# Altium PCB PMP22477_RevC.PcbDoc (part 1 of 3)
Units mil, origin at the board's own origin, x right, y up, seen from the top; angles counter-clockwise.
Board outline 5000 x 3000 mil, 4 copper layers (Top Layer, Signal Layer 1, Signal Layer 2, Bottom Layer), stack 61.2 mil thick; 191 components, 134 nets, 569 pads, 237 vias.
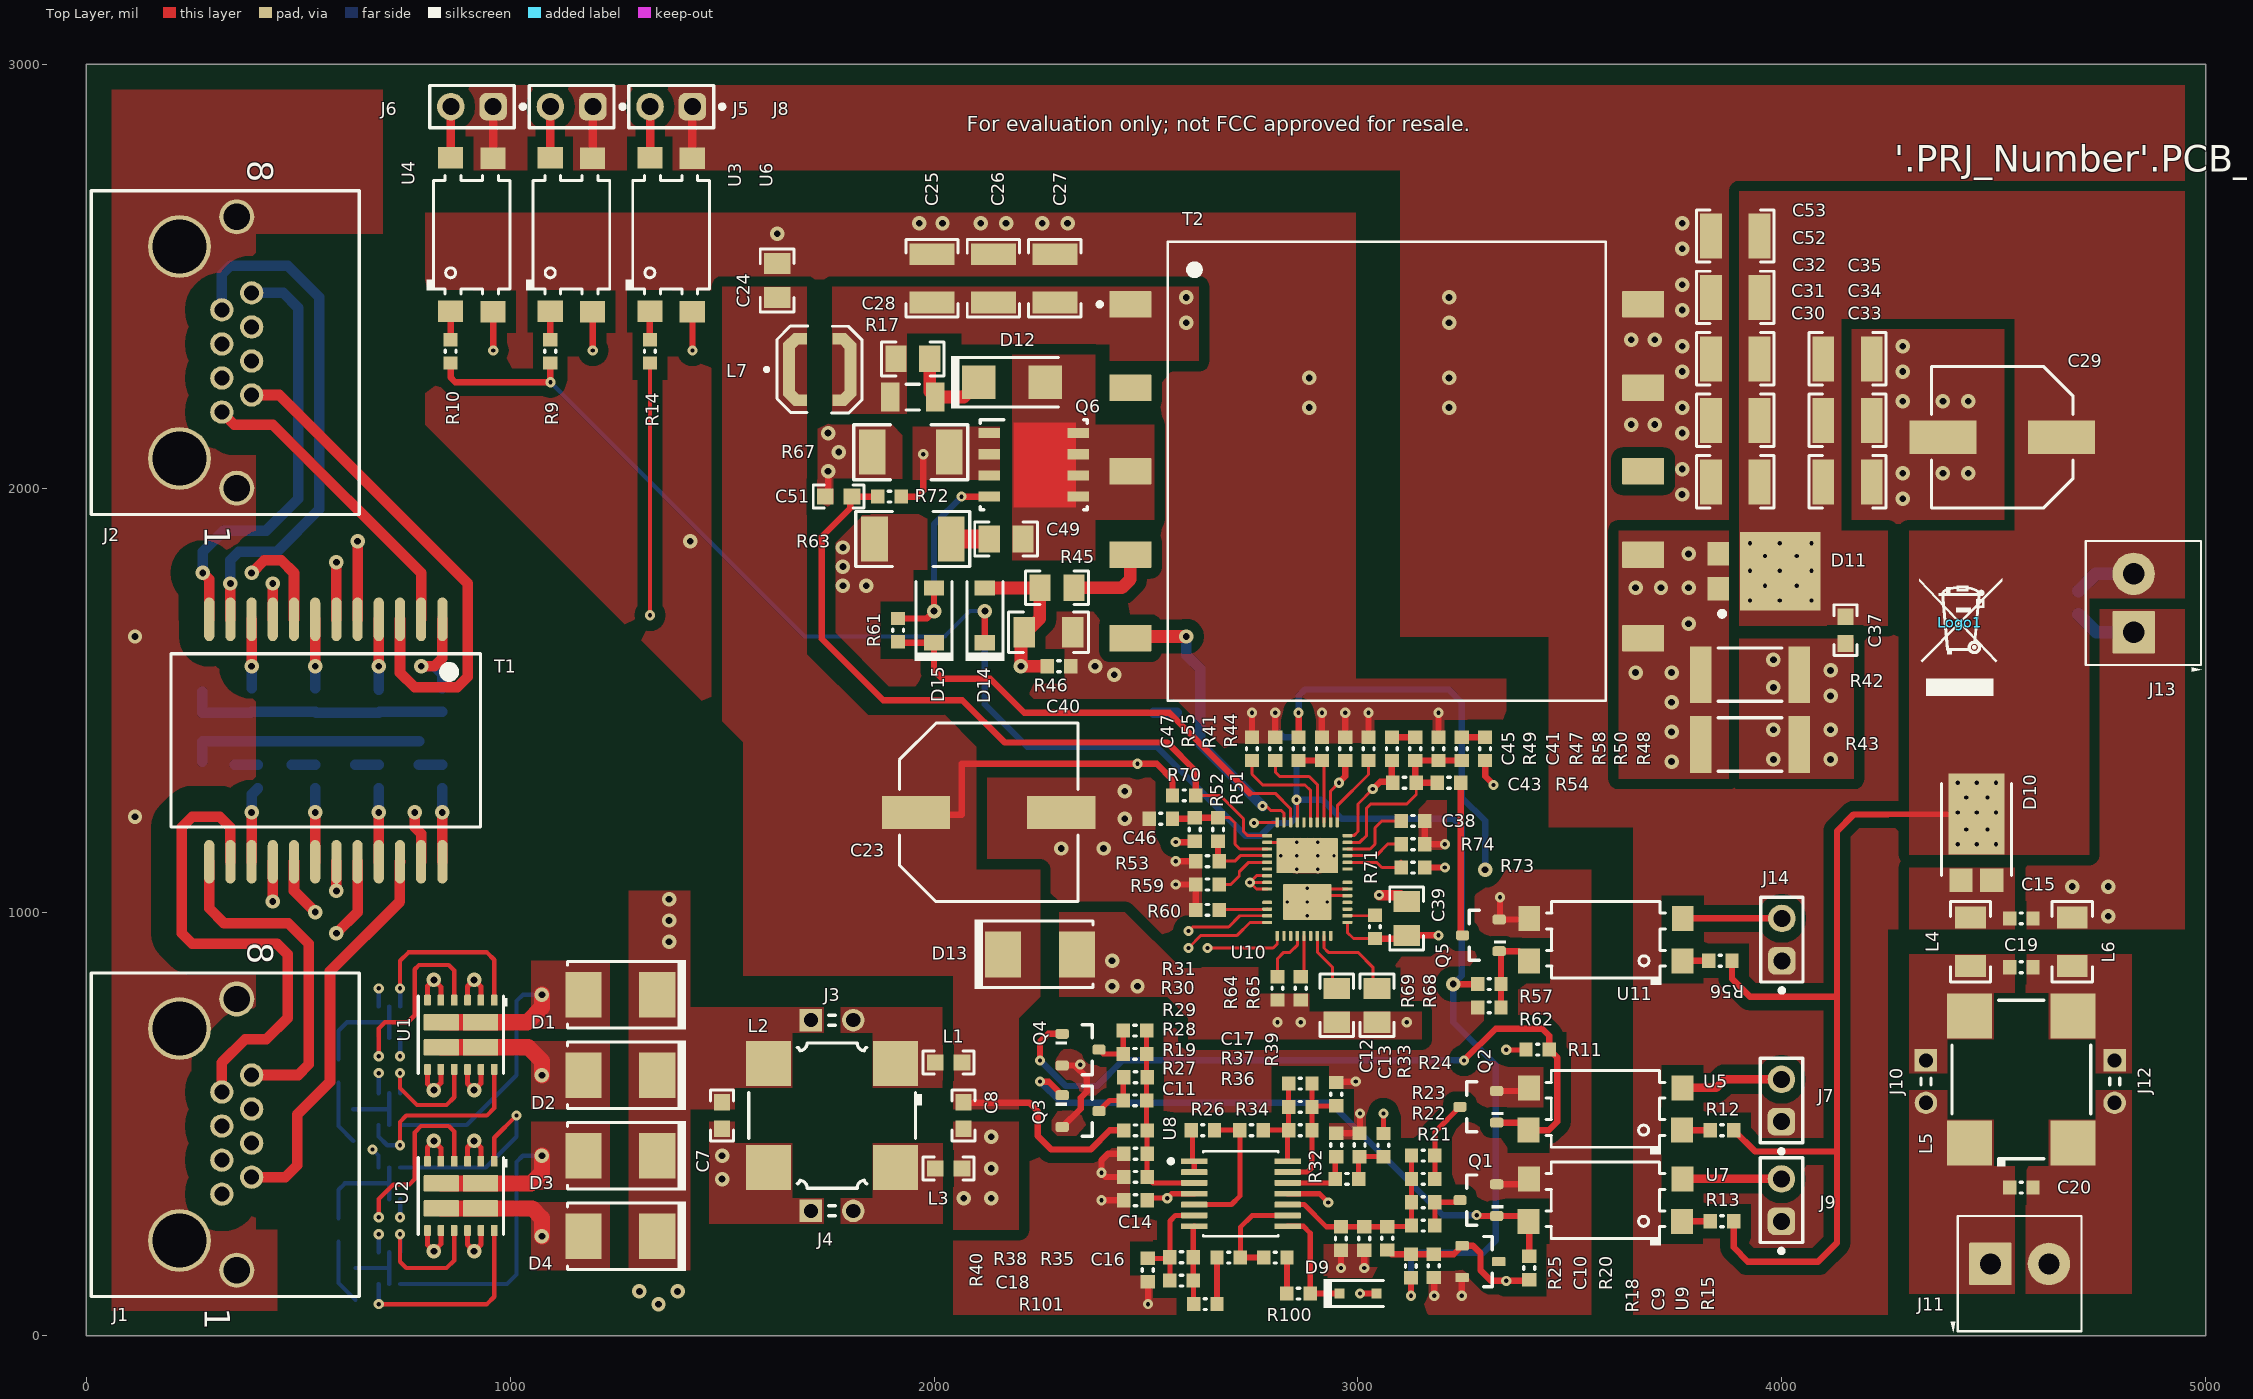
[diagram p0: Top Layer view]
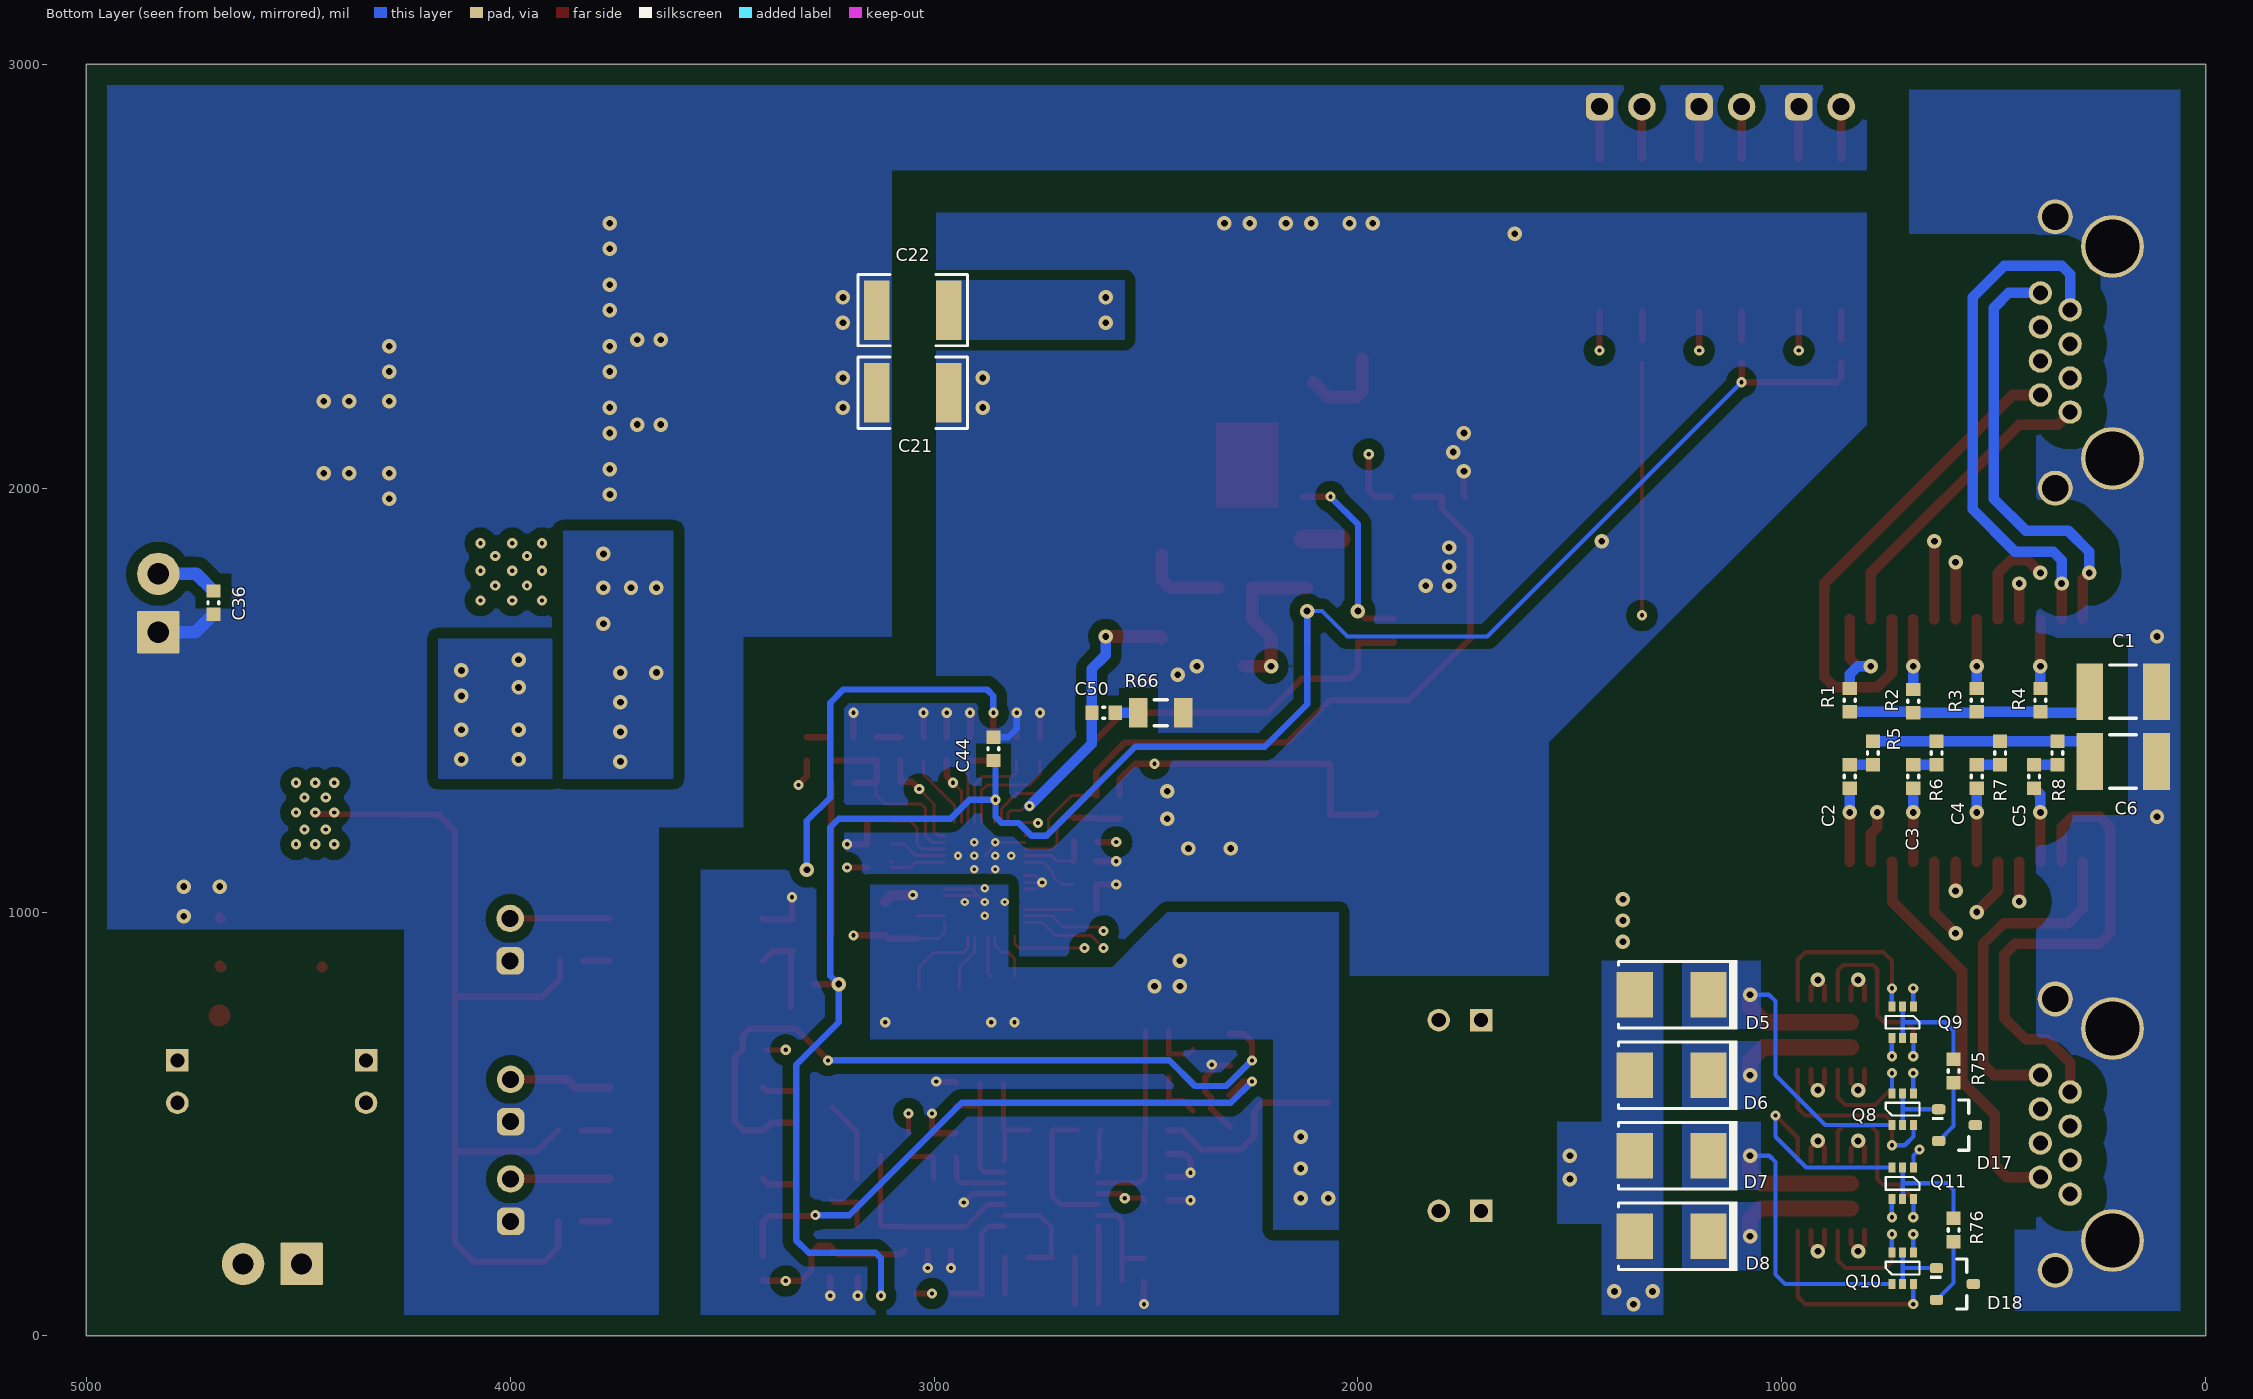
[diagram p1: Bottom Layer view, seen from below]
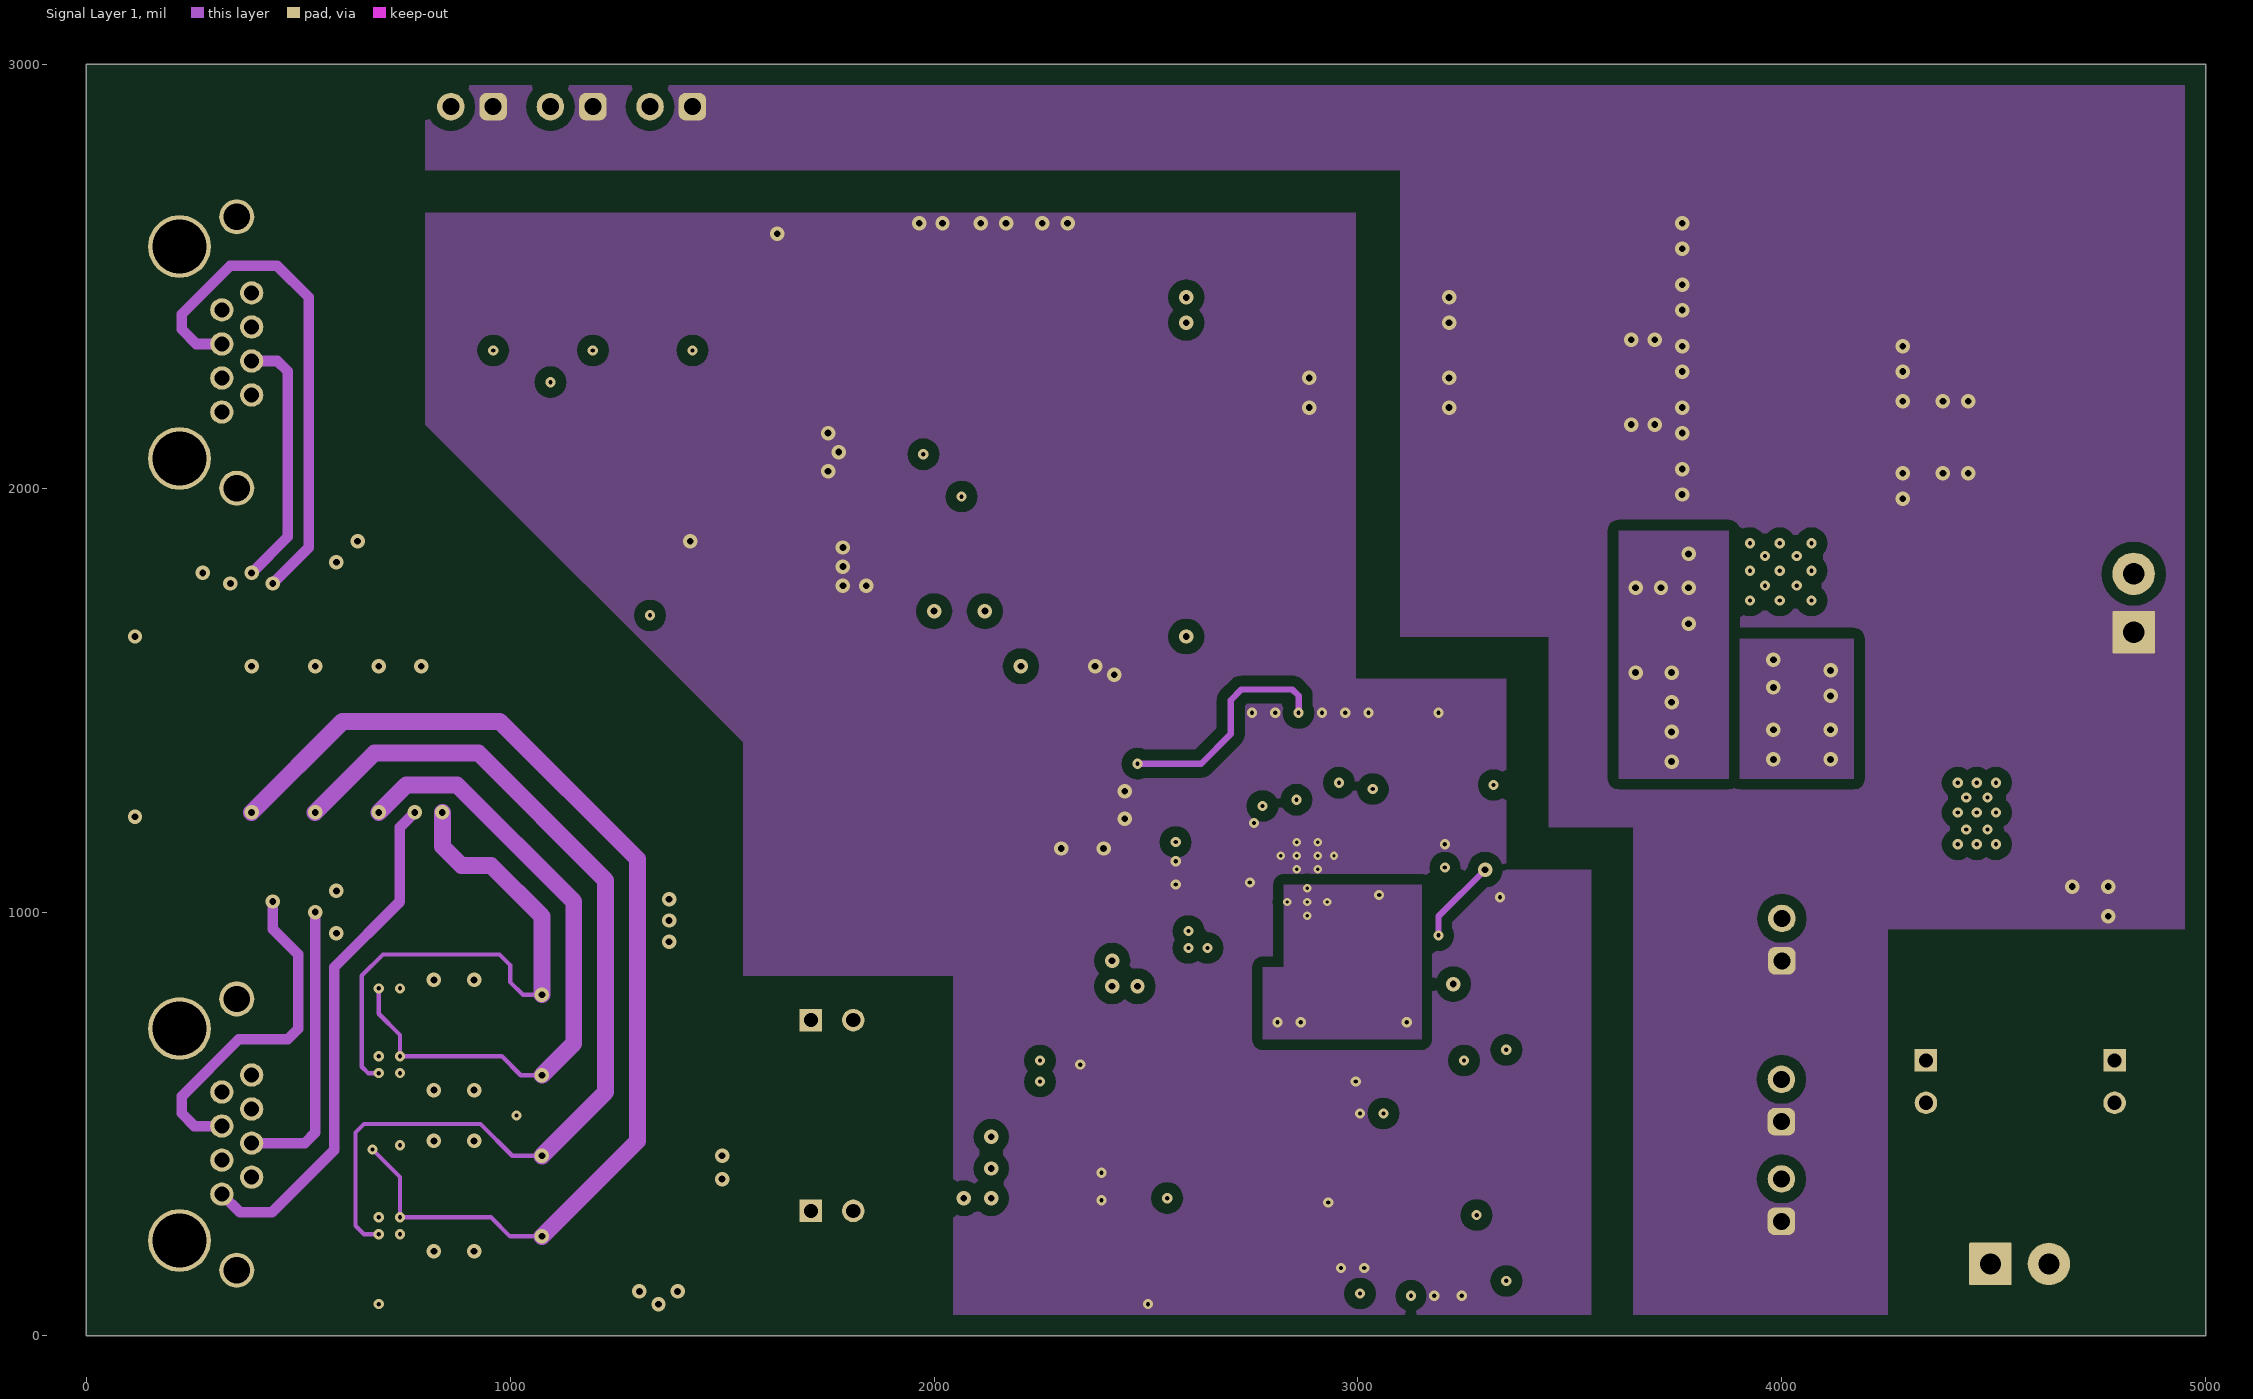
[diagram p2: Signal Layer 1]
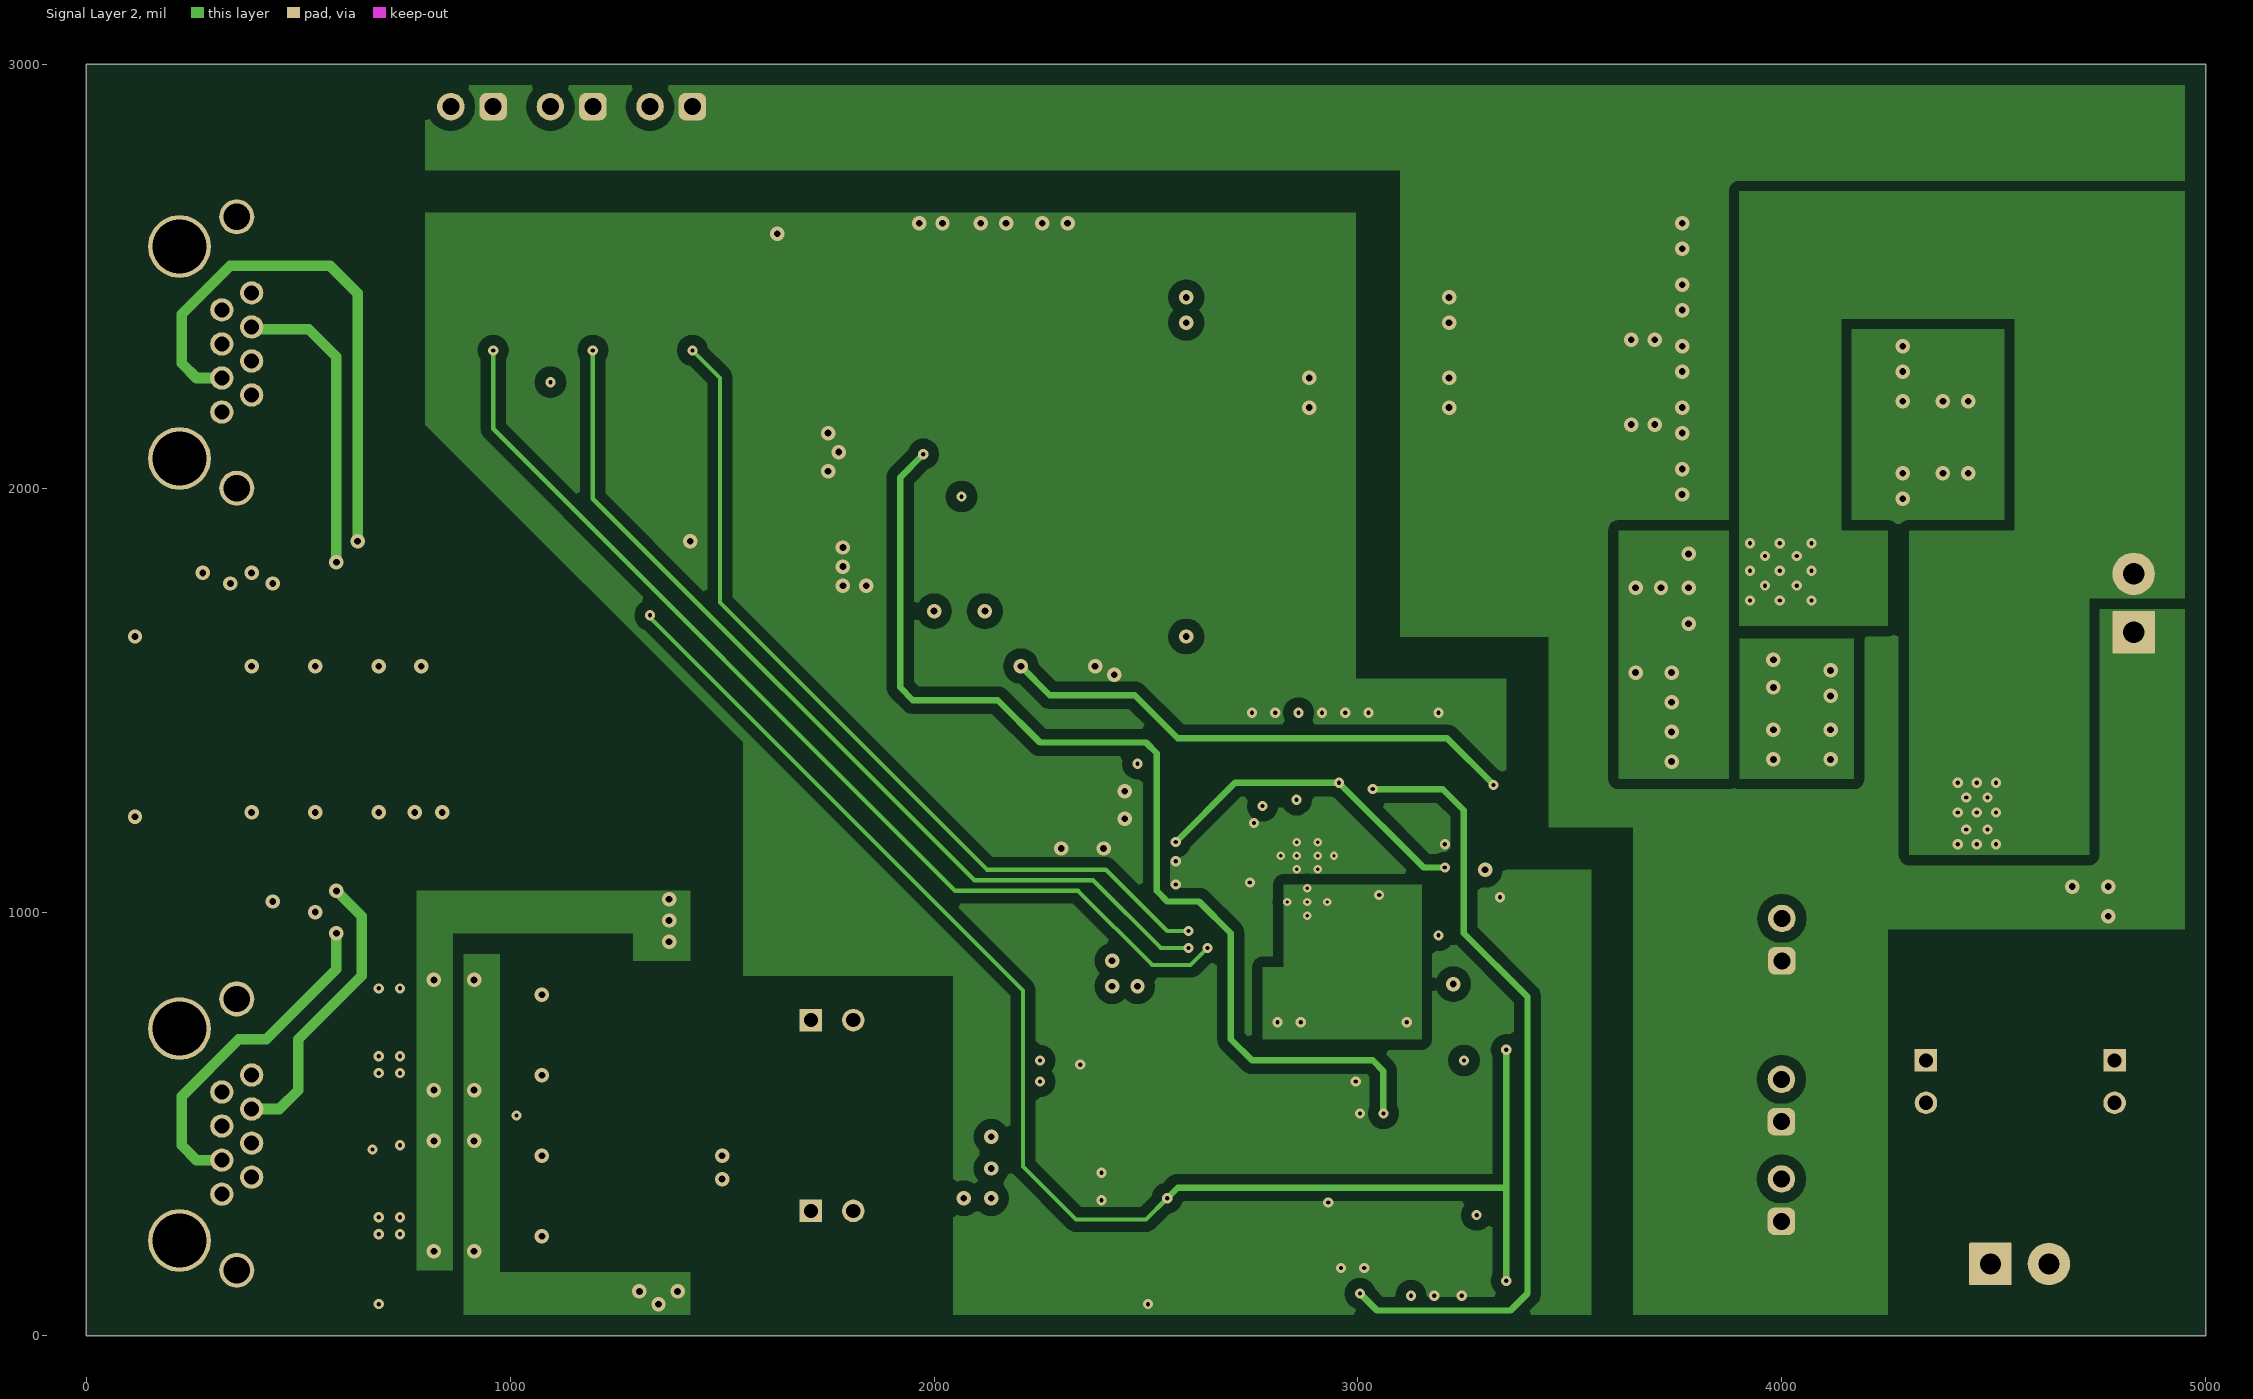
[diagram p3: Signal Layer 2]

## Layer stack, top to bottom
Top Solder: solder mask 0.4, Solder Resist, Dk 3.5
Top Layer: signal copper 2.8
Dielectric1: core 15, FR-4, Dk 4.8
Signal Layer 1: signal copper 2.8
Dielectric 2: prepreg 20, Dk 4.2
Signal Layer 2: signal copper 2.8
Dielectric 3: core 15, Dk 4.2
Bottom Layer: signal copper 2.8
Bottom Solder: solder mask 0.4, Solder Resist, Dk 3.5

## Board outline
0,0 5000,0 5000,3000 0,3000

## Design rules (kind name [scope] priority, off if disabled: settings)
AcuteAngle [All] p1: minimum=4.50000000000000E+0001 checktracksonly=FALSE
AssemblyTestPointUsage [All] p1: valid=2
BoardOutlineClearance BoardOutlineClearance_MountingHoles [OnCopper and InComponentClass('Mounting Holes')] p1: gap=39.37 ignorepadtopadclearanceinfootprint=FALSE
BoardOutlineClearance BoardOutlineClearance_Poly [OnCopper and IsPoly] p2: gap=25 ignorepadtopadclearanceinfootprint=FALSE
BoardOutlineClearance [OnCopper and Not InComponentClass('Logo') and not InComponentClass('FiducialMark') and not InRegion(1000,500,4000,800) and not InPoly] p3: gap=50 ignorepadtopadclearanceinfootprint=FALSE
Clearance Clearance_2 [InNamedPolygon('BOTTOM_LAYER_BSP_P106')] p1: gap=60 ignorepadtopadclearanceinfootprint=FALSE
Clearance Clearance_1 [InNamedPolygon('TOP_LAYER_BSP_P104')] p2: gap=60 ignorepadtopadclearanceinfootprint=FALSE
Clearance Clearance_Keepouts [((IsTrack Or IsArc) And Not InPoly) And IsFree and IsKeepOut vs ((IsTrack Or IsArc) And Not InPoly) And IsFree and IsKeepOut] p3: gap=0 ignorepadtopadclearanceinfootprint=FALSE
Clearance Clearance_Poly [InPolygon] p4: gap=25 ignorepadtopadclearanceinfootprint=TRUE
Clearance Clearance_FiducialMark [IsKeepOut and InComponentClass('FiducialMark') vs IsPad and InComponentClass('FiducialMark')] p5: gap=0 ignorepadtopadclearanceinfootprint=FALSE
Clearance [All] p6: gap=7.87 ignorepadtopadclearanceinfootprint=TRUE
ComponentClearance ComponentClearance_MountingHoles_FiducialMarks [InComponentClass('Mounting Holes') vs InComponentClass('FiducialMark')] p1: gap=50 collisioncheckmode=3 verticalgap=10 showdistances=FALSE
ComponentClearance ComponentClearance_Shunt [InComponentClass('Header') vs InComponentClass('Shunt')] p2: gap=0 collisioncheckmode=3 verticalgap=0 showdistances=FALSE
ComponentClearance ComponentClearance_Logo [InComponentClass('Logo')] p3: gap=50 collisioncheckmode=3 verticalgap=10 showdistances=FALSE
ComponentClearance ComponentClearance_ScrewToNut [(HasFootprint('NY PMS 440 0025 PH')) vs (HasFootprint('Keystone_1902C'))] p4: gap=5 collisioncheckmode=3 verticalgap=10 showdistances=FALSE
ComponentClearance ComponentClearance_MountingHoles [InComponentClass('Mounting Holes')] p5: gap=250 collisioncheckmode=3 verticalgap=100000 showdistances=FALSE
ComponentClearance ComponentClearance_SmallPassives [HasFootprint('0201*') or HasFootprint('0402*') or HasFootprint('0508') or HasFootprint('0603*') or HasFootprint('0612') or HasFootprint('0805*') or HasFootprint('0815*') or HasFootprint('0830*') or HasFootprint('1206*') or HasFootprint('1210*') or HasFootprint('1808*') or HasFootprint('1812*') or HasFootprint('1825*') or HasFootprint('2010*') or HasFootprint('2220*') or HasFootprint('2225*') or HasFootprint('2512*') or HasFootprint('2728*') or HasFootprint('3518*') vs HasFootprint('0201*') or HasFootprint('0402*') or HasFootprint('0508') or HasFootprint('0603*') or HasFootprint('0612') or HasFootprint('0805*') or HasFootprint('0815*') or HasFootprint('0830*') or HasFootprint('1206*') or HasFootprint('1210*') or HasFootprint('1808*') or HasFootprint('1812*') or HasFootprint('1825*') or HasFootprint('2010*') or HasFootprint('2220*') or HasFootprint('2225*') or HasFootprint('2512*') or HasFootprint('2728*') or HasFootprint('3518*')] p6: gap=14.96 collisioncheckmode=3 verticalgap=10 showdistances=FALSE
ComponentClearance ComponentClearance_THtoSMT [IsThruComponent vs IsSMTComponent] p7: gap=40 collisioncheckmode=3 verticalgap=30 showdistances=FALSE
ComponentClearance ComponentClearance_THtoTH [IsThruComponent vs IsThruComponent] p8: gap=30 collisioncheckmode=3 verticalgap=30 showdistances=FALSE
ComponentClearance [All] p9: gap=30 collisioncheckmode=3 verticalgap=10 showdistances=FALSE
DiffPairsRouting [All] p1: maxlimit=100 minlimit=10 mostfreqgap=10 toplayer_minwidth=15 toplayer_maxwidth=15 toplayer_prefwidth=15 midlayer1_minwidth=15 midlayer1_maxwidth=15 midlayer1_prefwidth=15 midlayer2_minwidth=15 midlayer2_maxwidth=15 midlayer2_prefwidth=15 bottomlayer_minwidth=15 bottomlayer_maxwidth=15 bottomlayer_prefwidth=15 maxuncoupledlength=1000
FabricationTestPointUsage TestPointUsage [All] p1: valid=2 allowmultiple=FALSE
FabricationTestpoint Testpoint [All] p1: side=3 testpointundercomponent=TRUE minsize=40 maxsize=100 preferedsize=60 minholesize=0 maxholesize=40 preferedholesize=32 testpointgrid=1 allowsidetop=TRUE allowsidebottom=TRUE usegrid=TRUE gridtolerance=0.01
FanoutControl Fanout_LCC [IsLCC] p1: bgadir=Out bgaviamode=Centered fanoutstyle=Auto fanoutdirection=Alternating viagrid=1 // Fanout_LCC (Default Rule)
FanoutControl Fanout_BGA [IsBGA] p2: bgadir=Out bgaviamode=Centered fanoutstyle=Auto fanoutdirection=Alternating viagrid=1 // Fanout_BGA (Default Rule)
FanoutControl Fanout_Default [All] p4: bgadir=Out bgaviamode=Centered fanoutstyle=Auto fanoutdirection=Alternating viagrid=1 // Fanout_Default (Default Rule)
FanoutControl Fanout_Small [(CompPinCount < 5)] p5: bgadir=Out bgaviamode=Centered fanoutstyle=Auto fanoutdirection=OutThenIn viagrid=1 // Fanout_Small (Default Rule)
HoleSize [All] p1: absolutevalues=TRUE maxlimit=251 minlimit=7.87 maxpercent=80.000 minpercent=20.000
MinimumAnnularRing MinimumAnnularRing_ThermalPadVias [IsVia and InAnyComponent] p1: minimumring=5.91
MinimumAnnularRing [All] p2: minimumring=7
MinimumSolderMaskSliver MinimumSolderMaskSliver_Logo [InComponentClass('Logo') vs InComponentClass('Logo')] p1: minsoldermaskwidth=0.7
MinimumSolderMaskSliver [All] p2: minsoldermaskwidth=3.94
PlaneConnect [All] p1: planeconnectstyle=Relief reliefexpansion=10 reliefentries=4 reliefconductorwidth=10 reliefairgap=10
PolygonConnect [All] p1: connectstyle=Direct reliefconductorwidth=10 reliefentries=4 polygonreliefangle="90 Angle" airgapwidth=10
RoutingVias ThermalPadVias [IsVia and InAnyComponent] p1: holewidth=7.87 width=19.68 viastyle="Through Hole" minholewidth=7.87 minwidth=19.68 maxholewidth=12.99 maxwidth=23.62
RoutingVias [All] p2: holewidth=16 width=34 viastyle="Through Hole" minholewidth=7.87 minwidth=24 maxholewidth=40 maxwidth=65
SilkToBoardRegionClearance [Not ((IsComment or IsDesignator) And (Hide <> 'False')) and not InRegion(1000,500,4000,800)] p1:
SilkToSilkClearance SilkToSilkClearance_Pb-FreeLogo [(HasFootprint('Pb-Free_Overlay_Medium') OR HasFootprint('Pb-Free_Overlay_Small')) vs (HasFootprint('Pb-Free_Overlay_Medium') OR HasFootprint('Pb-Free_Overlay_Small'))] p1: silktosilkclearance=0
SilkToSilkClearance [All] p2: silktosilkclearance=3.94
SilkToSolderMaskClearance SilkToComponentPadClearance [(IsPad or IsFill or IsRegion) and InAnycomponent] p1: minsilkscreentomaskgap=5 clearancetoexposedcopper=TRUE
SilkToSolderMaskClearance "Silk to Solder Mask Opening" [All] p2: minsilkscreentomaskgap=3.94 clearancetoexposedcopper=FALSE
SolderMaskExpansion [All] p1: expansion=1.97
UnRoutedNet [All] p1: checkbadconnections=TRUE
Width [All] p1: maxlimit=100 minlimit=6 preferedwidth=10 checkconnectedcopper=TRUE
14 further rules are at their usual default settings.

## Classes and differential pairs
component class PMP22477_RevC_SH2: C15 C19 C20 C21 C22 C23 C24 C25 C26 C27 C28 C29 C30 C31 C32 C33 C34 C35 C36 C37 C38 C39 C40 C41 C43 C44 C45 C46 C47 C49 C50 C51 C52 C53 D10 D11 D12 D13 D14 D15 J10 J11 J12 J13 J14 L4 L5 L6 L7 Q5 Q6 R17 R41 R42 R43 R44 R45 R46 R47 R48 R49 R50 R51 R52 R53 R54 R55 R56 R57 R58 R59 R60 R61 R62 R63 R64 R65 R66 R67 R68 R69 R70 R71 R72 R73 R74 T2 U10 U11
component class PMP22477_RevC_SH3: C9 C10 C11 C12 C13 C14 C16 C17 C18 D9 J5 J6 J7 J8 J9 Q1 Q2 Q3 Q4 R9 R10 R11 R12 R13 R14 R15 R18 R19 R20 R21 R22 R23 R24 R25 R26 R27 R28 R29 R30 R31 R32 R33 R34 R35 R36 R37 R38 R39 R40 R100 R101 U3 U4 U5 U6 U7 U8 U9
component class PMP22477_RevC_SH1: C1 C2 C3 C4 C5 C6 C7 C8 D1 D2 D3 D4 D5 D6 D7 D8 D17 D18 J1 J2 J3 J4 L1 L2 L3 Logo1 Logo2 Q8 Q9 Q10 Q11 R1 R2 R3 R4 R5 R6 R7 R8 R75 R76 T1 U1 U2
component class Header: J5 J6 J7 J8 J9 J14

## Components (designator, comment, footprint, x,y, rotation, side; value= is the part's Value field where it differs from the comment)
C1 "GR443QR73D102KW01L" 1812 195,1520 r0 bottom value=1000pF
C2 "Capacitor" 0603L 840,1320 r90 bottom value=0.01uF
C3 "Capacitor" 0603L 690,1320 r90 bottom value=0.01uF
C4 "Capacitor" 0603L 540,1320 r90 bottom value=0.01uF
C5 "Capacitor" 0603L 405,1320 r90 bottom value=0.01uF
C6 "GR443QR73D102KW01L" 1812 195,1355 r180 bottom value=1000pF
C7 "C1608X7R2A102K080AA" 0603 1500,520 r270 top value=1000pF
C8 "C1608X7R2A102K080AA" 0603 2069.43,520 r270 top value=1000pF
C9 "885012206083" 0603L 3178.98,165.46 r90 top value=1000pF
C10 "885012206083" 0603L 3015,230 r90 top value=1000pF
C11 "885012206083" 0603L 2475,375 r0 top value=1000pF
C12 "GRM188R71C473KA01D" 0603L 2948.98,450.46 r270 top value=0.047uF
C13 "GRM1885C1H471JA01D" 0603L 3003.98,450.46 r270 top value=470pF
C14 "GRM188R71H103KA01D" 0603L 2475,320 r0 top value=0.01uF
C15 "GRJ188R71E105KE11D" 0603L 4565,985 r0 top value=1uF
C16 "GRM188R71H103KA01D" 0603L 2805,185 r180 top value=0.01uF
C17 "GRM1885C1H271JA01D" 0603L 2863.98,595.46 r180 top value=270pF
C18 "885012206083" 0603L 2583.98,130.46 r0 top value=1000pF
C19 "C0603C104J3RACTU" 0603L 4565,870 r180 top value=0.1uF
C20 "C0603C104J3RACTU" 0603L 4565,350 r180 top value=0.1uF
C21 "Capacitor" 1812_HV 3050,2225 r180 bottom value=2200pF
C22 "Capacitor" 1812_HV 3050,2420 r180 bottom value=2200pF
C23 "EEE-FK1K470P" SM_RADIAL_G 2128.74,1235 r0 top value=47uF
C24 "Capacitor" 0805_HV 1630,2490 r90 top value=0.1uF
C25 "Capacitor" 1210_270 1995,2495 r90 top value=2.2uF
C26 "Capacitor" 1210_270 2140,2495 r90 top value=2.2uF
C27 "Capacitor" 1210_270 2285,2495 r90 top value=2.2uF
C28 "Capacitor" 0805_HV 1950,2305 r180 top value=0.1uF
C29 "EEE-FK1E221P" SM_RADIAL_F 4520,2120 r180 top value=220uF
C30 "GRM32ER71E226KE15L" 1210_270 3890,2015 r0 top value=22uF
C31 "GRM32ER71E226KE15L" 1210_270 3890,2160 r0 top value=22uF
C32 "GRM32ER71E226KE15L" 1210_270 3890,2305 r0 top value=22uF
C33 "GRM32ER71E226KE15L" 1210_270 4155,2015 r180 top value=22uF
C34 "GRM32ER71E226KE15L" 1210_270 4155,2160 r180 top value=22uF
C35 "GRM32ER71E226KE15L" 1210_270 4155,2305 r180 top value=22uF
C36 "GRJ188R71E105KE11D" 0603L 4700,1730 r270 bottom value=1uF
C37 "06031C222KAT2A" 0603 4150,1665 r270 top value=2200pF
C38 "GRM188R71C473KA01D" 0603L 3130,1215 r0 top value=0.047uF
C39 "Capacitor" 0805_HV 3115,985 r90 top value=0.1uF
C40 "GRJ188R71E105KE11D" 0603L 2295,1580 r0 top value=1uF
C41 "C1608X7R1H153K080AA" 0603L 3080,1385 r270 top value=0.015uF
C43 "GRM188R71H221KA01D" 0603L 3110,1305 r180 top value=220pF
C44 "GRJ188R71E105KE11D" 0603L 2860,1385 r90 bottom value=1uF
C45 "C0603C104J3RACTU" 0603L 2970,1385 r90 top value=0.1uF
C46 "C0603C222K5RAC" 0603L 2535,1220 r180 top value=2200pF
C47 "C0603C104J3RACTU" 0603L 2750,1385 r270 top value=0.1uF
C49 "GRM21A5C2E101JW01D" 0805_HV 2170,1880 r0 top value=100pF
C50 "885012206083" 0603L 2600,1470 r180 bottom value=1000pF
C51 "885012006057" 0603 1775,1980 r0 top value=100pF
C52 "GRM32ER71E226KE15L" 1210_270 3890,2450 r0 top value=22uF
C53 "GRM32ER71E226KE15L" 1210_270 3890,2595 r0 top value=22uF
D1 "CMP-0028397-2" SMB 1260,805 r180 top value=100V
D2 "CMP-0028397-2" SMB 1260,615 r180 top value=100V
D3 "CMP-0028397-2" SMB 1260,425 r180 top value=100V
D4 "CMP-0028397-2" SMB 1260,235 r180 top value=100V
D5 "CMP-0028397-2" SMB 1260,805 r0 bottom value=100V
D6 "CMP-0028397-2" SMB 1260,615 r0 bottom value=100V
D7 "CMP-0028397-2" SMB 1260,425 r0 bottom value=100V
D8 "CMP-0028397-2" SMB 1260,235 r0 bottom value=100V
D9 "BAS316,115" SOD-323 3000,100 r0 top value=100V
D10 "PDS1040L-13" POWERDI5 4458.78,1153.39 r90 top value=40V
D11 "FSV1060V" TO-277A 3922.05,1804.06 r90 top value=60V
D12 "ES1D-13-F" SMA 2183.74,2250 r0 top value=200V
D13 "SMBJ58A-13-F" SMB 2250,900 r0 top value=58V
D14 "MMSD4148T1G" SOD-123 2120,1700 r90 top value=100V
D15 "MMSD4148T1G" SOD-123 2000,1700 r90 top value=100V
D17 "MMBZ27VALT1G" SOT-23L 586.69,497.4 r180 bottom value=27V
D18 "MMBZ27VALT1G" SOT-23L 591.69,122.6 r180 bottom value=27V
J1 "1-406541-1" TEC_1-406541-1 327.05,474.68 r270 top
J2 "1-406541-1" TEC_1-406541-1 327.05,2319.68 r270 top
J3 "999-11-110-10-000000" Mill-Max_999-11-110-10-000000 1759.43,745 r0 top
J4 "999-11-110-10-000000" Mill-Max_999-11-110-10-000000 1759.43,295 r0 top
J5 "TSW-102-07-G-S" TSW-102-07-G-S 1145,2900 r180 top
J6 "TSW-102-07-G-S" TSW-102-07-G-S 910,2900 r180 top
J7 "TSW-102-07-G-S" TSW-102-07-G-S 3998.98,555.46 r90 top
J8 "TSW-102-07-G-S" TSW-102-07-G-S 1380,2900 r180 top
J9 "TSW-102-07-G-S" TSW-102-07-G-S 3998.98,320.46 r90 top
J10 "999-11-110-10-000000" Mill-Max_999-11-110-10-000000 4340,600 r270 top
J11 "CMP-0074913-1" TERM_BLK_ED555-2DS 4492,170 r0 top
J12 "999-11-110-10-000000" Mill-Max_999-11-110-10-000000 4785,600 r270 top
J13 "Receptacle_2x1" TERM_BLK_ED555-2DS 4830,1660 r90 top
J14 "TSW-102-07-G-S" TSW-102-07-G-S 4000,935 r90 top
L1 "CMP-0003192-2" 0603 2034.43,645 r0 top value="300 ohm"
L2 "744272251" WE-SL5 1759.43,520 r270 top value=250uH
L3 "CMP-0003192-2" 0603 2034.43,395 r0 top value="300 ohm"
L4 "742792115" 1206 4445,930 r270 top value="80 ohm"
L5 "744273501" WE-SL5_HC 4565,605 r90 top value=5uH
L6 "742792115" 1206 4685,930 r270 top value="80 ohm"
L7 "LPS4018-332MLB" LPS4018 1730,2280 r0 top value=3.3uH
Logo1 "WEEE logo" WEEE_Minimum 4420,1682.76 r0 top
Logo2 "FCC disclaimer" FCC_disclaimer 6515.75,187.01 r0 top
Q1 "2N7002-7-F" SOT-23L 3283.98,320.46 r180 top value=60V
Q2 "2N7002-7-F" SOT-23L 3283.98,540.46 r180 top value=60V
Q3 "2N7002-7-F" SOT-23L 2345.67,530.46 r0 top value=60V
Q4 "2N7002-7-F" SOT-23L 2345.67,675.46 r0 top value=60V
Q5 "2N7002-7-F" SOT-23L 3290,945 r180 top value=60V
Q6 "FDMS86252" TRANS_Fairchild_PQFN08A 2235.12,2055 r0 top value=150V
Q8 "BC 846PN H6327" SOT-363 715,535 r90 bottom value="65 V"
Q9 "BC 846PN H6327" SOT-363 715,740 r270 bottom value="65 V"
Q10 "BC 846PN H6327" SOT-363 715,160 r90 bottom value="65 V"
Q11 "BC 846PN H6327" SOT-363 715,360 r270 bottom value="65 V"
R1 "Resistor" 0603L 840,1500 r270 bottom value=75.0
R2 "Resistor" 0603L 690,1497.44 r270 bottom value=75.0
R3 "Resistor" 0603L 540,1500 r270 bottom value=75.0
R4 "Resistor" 0603L 390,1500 r90 bottom value=75.0
R5 "Resistor" 0603L 785,1375 r270 bottom value=75.0
R6 "Resistor" 0603L 635,1375 r270 bottom value=75.0
R7 "Resistor" 0603L 485,1375 r270 bottom value=75.0
R8 "Resistor" 0603L 350,1375 r270 bottom value=75.0
R9 "CRCW060310K0FKEA" 0603L 1094.54,2322.91 r270 top value=10.0k
R10 "CRCW060310K0FKEA" 0603L 859.54,2322.91 r270 top value=10.0k
R11 "CRCW060310K0FKEA" 0603L 3423.98,675.46 r0 top value=10.0k
R12 "CRCW060310K0FKEA" 0603L 3858.98,485.46 r180 top value=10.0k
R13 "CRCW060310K0FKEA" 0603L 3858.98,270.46 r180 top value=10.0k
R14 "CRCW06034K99FKEA" 0603L 1329.54,2322.91 r90 top value=4.99k
R15 "CRCW060310K0FKEA" 0603L 3403.98,160.46 r90 top value=10.0k
R17 "Resistor" 1206L 1950,2215 r180 top value=39k
R18 "CRCW06031K00FKEA" 0603L 3125,165 r270 top value=1.00k
R19 "CRCW0603100KFKEA" 0603L 2475,485 r180 top value=100k
R20 "CRCW060310K0FKEA" 0603L 3068.98,230.46 r270 top value=10.0k
R21 "CRCW0603196KFKEA" 0603L 3153.98,260.46 r0 top value=196k
R22 "CRCW06038K06FKEA" 0603L 3153.98,315.46 r0 top value=8.06k
R23 "CRCW06031M00FKEA" 0603L 3153.98,370.46 r180 top value=1.00Meg
R24 "CRCW06032K94FKEA" 0603L 3153.98,425.46 r0 top value=2.94k
R25 "CRCW060340K2FKEA" 0603L 2960,230 r270 top value=40.2k
R26 "CRCW06031K00FKEA" 0603L 2633.98,485.46 r0 top value=1.00k
R27 "CRCW06034K22FKEA" 0603L 2475,430 r0 top value=4.22k
R28 "CRCW0603280KFKEA" 0603L 2473.98,555.46 r180 top value=280k
R29 "CRCW06033K92FKEA" 0603L 2475,610.1 r180 top value=3.92k
R30 "CRCW060340K2FKEA" 0603L 2473.98,665.46 r180 top value=40.2k
R31 "CRCW06031K69FKEA" 0603L 2473.98,720.46 r180 top value=1.69k
R32 "CRCW0603100RFKEA" 0603L 2973.98,370.46 r0 top value=100
R33 "CRCW0603100RFKEA" 0603L 3060,450 r90 top value=100
R34 "CRCW06031K00FKEA" 0603L 2748.98,485.46 r0 top value=1.00k
R35 "CRCW060310K0FKEA" 0603L 2695,185 r180 top value=10.0k
R36 "CRCW06031M00FKEA" 0603L 2863.98,485.46 r180 top value=1.00Meg
R37 "CRCW060340K2FKEA" 0603L 2863.98,540.46 r0 top value=40.2k
R38 "CRCW06031K00FKEA" 0603L 2583.98,185.46 r180 top value=1.00k
R39 "CRCW06031K00FKEA" 0603L 2948.98,570.46 r90 top value=1.00k
R40 "CRCW06031K00FKEA" 0603L 2503.98,155.46 r90 top value=1.00k
R41 "CRCW0603110KFKEA" 0603L 2860,1385 r90 top value=110k
R42 "CRCW251215R0JNEG" 2512 3925,1560 r0 top value=15
R43 "CRCW251215R0JNEG" 2512 3925,1395 r0 top value=15
R44 "CRCW060310K0FKEA" 0603L 2915,1385 r270 top value=10.0k
R45 "ERJ-6RQF3R9V" 0805_HV 2290,1765 r0 top value=3.90
R46 "CRCW12063K00JNEA" 1206 2270,1660 r180 top value=3.0k
R47 "CRCW060339K2FKEA" 0603L 3135,1385 r270 top value=39.2k
R48 "ERJ-3GEY0R00V" 0603L 3300,1385 r270 top value=0
R49 "ERJ-3GEY0R00V" 0603L 3025,1385 r90 top value=0
R50 "RC0603FR-0724K9L" 0603L 3245,1385 r90 top value=24.9k
R51 "RC0603FR-07237KL" 0603L 2670,1195 r270 top value=237k
R52 "ERJ-3GEY0R00V" 0603L 2615,1195 r90 top value=0
R53 "CRCW060360K4FKEA" 0603L 2645,1120 r0 top value=60.4k
R54 "RC0603FR-0735K7L" 0603L 3215,1305 r0 top value=35.7k
R55 "ERJ-3GEY0R00V" 0603L 2805,1385 r90 top value=0
R56 "CRCW060310K0FKEA" 0603L 3855,885 r180 top value=10.0k
R57 "CRCW060320K0FKEA" 0603L 3310,830 r0 top value=20.0k
R58 "CRCW06034K99FKEA" 0603L 3190,1385 r90 top value=4.99k
R59 "ERJ-3GEY0R00V" 0603L 2645,1065 r0 top value=0
R60 "ERJ-3GEY0R00V" 0603L 2645,1005 r0 top value=0
R61 "CRCW06034R70JNEA" 0603L 1915,1665 r90 top value=4.7
R62 "CRCW060320K0FKEA" 0603L 3310,775 r180 top value=20.0k
R63 "CRCW201075R0JNEF" 2010 1950,1880 r180 top value=75
R64 "CRCW060349K9FKEA" 0603L 2810,820 r90 top value=49.9k
R65 "ERJ-3GEY0R00V" 0603L 2865,820 r90 top value=0
R66 "CRCW120615R0JNEA" 1206L 2465,1470 r180 bottom value=15
R67 "CSRN2010FK50L0" 2010 1945,2085 r180 top value=0.05
R68 "CRCW080531R6FKEA" 0805_HV 3045,780 r90 top value=31.6
R69 "CRCW0805130RFKEA" 0805_HV 2950,780 r90 top value=130
R70 "CRCW0603750KJNEA" 0603L 2590,1275 r180 top value=750k
R71 "RC0603FR-0725K5L" 0603L 3040,965 r90 top value=25.5k
R72 "CRCW06031K00FKEA" 0603L 1895,1980 r0 top value=1.00k
R73 "ERJ-3GEY0R00V" 0603L 3130,1105 r180 top value=0
R74 "CRCW0603499KFKEA" 0603L 3130,1160 r180 top value=499k
R75 "CRCW0603162KFKEA" 0603L 595,625 r270 bottom value=162k
R76 "CRCW0603162KFKEA" 0603L 595,250 r270 bottom value=162k
R100 "CRCW06033K01FKEA" 0603L 2860,100 r180 top value=3.01k
R101 "ERJ-3GEY0R00V" 0603L 2640,75 r0 top value=0
T1 "749022016" XFMR_749022016 565.04,1404.63 r270 top value=350uH
T2 "LDT9055-51R" FP-LDT9055-B_SMT_27MM5_26MM0-MFG 3068.03,2039.92 r0 top
U1 "FDMQ8205A" MLP-4_5x5 883.74,710.47 r270 top
U2 "FDMQ8205A" MLP-4_5x5 883.74,330.47 r270 top
U3 "FOD817DS" N04C 1144.54,2597.91 r90 top
U4 "FOD817DS" N04C 909.54,2597.91 r90 top
U5 "FOD817DS" N04C 3583.98,535.46 r180 top
U6 "FOD817DS" N04C 1379.54,2597.91 r90 top
U7 "FOD817DS" N04C 3583.98,320.46 r180 top
U8 "TLV4376IPWR" PW0014A-MFG 2723.98,335.46 r0 top
U9 "LM4040DIM3-5.0/NOPB" DBZ0003A_L 3288.98,175.46 r0 top
U10 "TPS23730RMT" RMT0045A 2880.51,1077.87 r0 top
U11 "FOD817DS" N04C 3585,935 r180 top

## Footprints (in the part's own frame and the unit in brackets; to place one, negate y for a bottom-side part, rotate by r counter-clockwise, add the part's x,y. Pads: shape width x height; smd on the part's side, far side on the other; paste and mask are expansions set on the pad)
0603 [mm] "0603 from SM-752 data"
  rect 1x0.95 smd: 1(-0.8,0) 2(0.8,0)
  silkscreen extent -1.52,-0.69 1.52,0.69, body extent -0.87,-0.47 0.87,0.47, height 1
0603L [mm] "0603 from SM-752 data"
  rect 0.8x0.85 smd: 1(-0.7,0) 2(0.7,0)
  silkscreen extent -0.07,-0.33 0.07,0.33, body extent -0.87,-0.47 0.87,0.47, height 1
0805_HV [mil] "0805 with 30mil clearance between pads"
  rect 50x63 smd: 1(-40,0) 2(40,0)
  silkscreen extent -74,-40 74,40, body extent -43,-29 43,29, height 57
1206 [mm] "1206 from SM-752 data"
  rect 1.3x1.85 smd: 1(-1.45,0) 2(1.45,0)
  silkscreen extent -2.4,-1.21 2.4,1.21, body extent -1.7,-0.9 1.7,0.9, height 1.35
1206L [mm] "1206 from SM-752 data"
  rect 1.1x1.75 smd: 1(-1.35,0) 2(1.35,0)
  silkscreen extent -0.4,-0.77 0.4,0.77, body extent -1.7,-0.9 1.7,0.9, height 1.35
1210_270 [mm] "1210"
  rect 1.3x2.7 smd: 1(-1.45,0) 2(1.45,0)
  silkscreen extent -2.32,-1.57 2.32,1.57, body extent -1.7,-1.35 1.7,1.35, height 2.7
1812 [mm]
  rect 1.6x3.4 smd: 1(-2,0) 2(2,0)
  silkscreen extent -0.8,-1.6 0.8,1.6, body extent -2.4,-1.7 2.4,1.7, height 1.35
1812_HV [mil] "PRG recommended land pattern"
  rect 60x140 smd: 1(-85,0) 2(85,0)
  silkscreen extent -129,-84 129,84, body extent -94,-67 94,67, height 53
2010 [mm] "Chip Capacitor, Body 5.08x2.54mm, IPC Medium Density"
  rect 1.6x2.7 smd: 1(-2.3,0) 2(2.3,0)
  silkscreen extent -3.42,-1.65 3.42,1.65, body extent -2.73,-1.45 2.73,1.45, height 1.66
2512 [mm] "Chip Resistor, Body 6.3x3.2mm, IPC Medium Density"
  rect 1.3x3.4 smd: 1(-2.95,0) 2(2.95,0)
  silkscreen extent -1.9,-1.6 1.9,1.6, body extent -3.22,-1.67 3.22,1.67, height 0.71
DBZ0003A_L [mm] "SOT23, 3-Leads, Body 2.9x1.3mm, Pitch 0.95mm, Lead Span 2.4mm, IPC High Density"
  rrect18% 0.8x0.55 smd: 1(-1.1,0.95) 2(-1.1,-0.95) 3(1.1,0)
  silkscreen extent 0.2,-1.5 0.7,1.5, body extent -1.26,-1.46 1.26,1.46, height 0.98
FCC_disclaimer [mil]
FP-LDT9055-B_SMT_27MM5_26MM0-MFG [mm]
  rrect6% 2.52x1.6 smd paste+0 mask+0: 1(-15.365,10) 2(-15.365,5) 3(-15.365,0) 4(-15.365,-5) 5(-15.365,-10) 6(15.365,-10) 7(15.365,-5) 8(15.365,0) 9(15.365,5) 10(15.365,10)
  silkscreen extent -17.32,-13.75 13.13,13.75, body extent -16.73,-13.85 16.73,13.85, height 0.25
LPS4018 [mil]
  rect 28x123 smd: 1(-72.5,0) 2(72.5,0)
  rect 35.5x28 smd rot 135: 1(-64,-64) 2(64,64)
  rect 35.5x28 smd rot 45: 1(-64,64) 2(64.5,-63.5)
  rect 31.5x28 smd: 1(-46,-72.5) 1(-46,72.5) 2(46,-72.5) 2(46,72.5)
  silkscreen extent -129,-102 100,102, body extent -81,-81 81,81, height 71
Mill-Max_999-11-110-10-000000 [mm] "Shorting Jumper, 2.54mm, 2 Position, Gold, TH"
  rect 1.35x1.35 hole 0.85: 1(-1.27,0)
  round 1.35 hole 0.85: 2(1.27,0)
  silkscreen extent -0.2,-0.3 0.2,0.3, body extent -1.55,-0.28 1.55,0.28, height 1.9
MLP-4_5x5 [mm] "MLP, 12-Leads, Body 4.5x5mm, Pitch 0.8mm"
  rrect25% 0.65x0.4 smd: 1(-2.075,2) 2(-2.075,1.2) 3(-2.075,0.4) 4(-2.075,-0.4) 5(-2.075,-1.2) 6(-2.075,-2) 7(2.075,-2) 8(2.075,-1.2) 9(2.075,-0.4) 10(2.075,0.4) 11(2.075,1.2) 12(2.075,2)
  rrect10% 1x2.1 smd: 13(-0.75,1.175) 14(-0.75,-1.175) 15(0.75,-1.175) 16(0.75,1.175)
  silkscreen extent -2.3,-2.55 2.3,2.8, body extent -2.3,-2.55 2.3,2.55, height 0.8
N04C [mm] "FAIRCHILD"
  rect 1.3x1.5 smd mask+0.065: 1(-4.587,1.27) 2(-4.612,-1.27) 3(4.588,-1.27) 4(4.613,1.27)
  silkscreen extent -3.56,-2.3 3.56,2.72, body extent -5.08,-2.3 5.08,2.3, height 3.87
POWERDI5 [mm] "Diodes Inc recommended land pattern, ap02001.pdf rev 60"
  rect 1.4x1.39 smd: 1(-1.991,0.92) 2(-1.991,-0.92)
  rect 4.86x3.36 smd: 3(1.991,0)
  silkscreen extent -1.7,-2.1 3.8,2.1, body extent -2.27,-2.03 4.33,2.03, height 1.17
PW0014A-MFG [mm]
  rrect29% 1.6x0.35 smd paste-1000 mask+0: 1(-2.8,1.95) 2(-2.8,1.3) 3(-2.8,0.65) 4(-2.8,0) 5(-2.8,-0.65) 6(-2.8,-1.3) 7(-2.8,-1.95) 8(2.8,-1.95) 9(2.8,-1.3) 10(2.8,-0.65) 11(2.8,0) 12(2.8,0.65) 13(2.8,1.3) 14(2.8,1.95)
  silkscreen extent -4.32,-2.55 2.25,2.55, body extent -3.7,-2.8 3.7,2.8, height 0.25
RMT0045A [mm] "VQFN-45"
  rrect50% 0.6x0.2 smd: 1(-2.4,2.6) 2(-2.4,2.2) 3(-2.4,1.8) 4(-2.4,1.4) 5(-2.4,1) 6(-2.4,0.6) 7(-2.4,0.2) 8(-2.4,-0.2) 9(-2.4,-0.6) 10(-2.4,-1.4) 11(-2.4,-1.8) 12(-2.4,-2.2) 13(-2.4,-2.6) 23(2.4,-2.6) 24(2.4,-2.2) 25(2.4,-1.8) 26(2.4,-1.4) 27(2.4,-1) 28(2.4,-0.6) 29(2.4,-0.2) 30(2.4,0.6) 31(2.4,1) 32(2.4,1.4) 33(2.4,1.8) 34(2.4,2.2) 35(2.4,2.6)
  rrect50% 0.2x0.6 smd: 14(-1.8,-3.4) 15(-1.4,-3.4) 16(-1,-3.4) 17(-0.6,-3.4) 18(-0.2,-3.4) 19(0.2,-3.4) 20(0.6,-3.4) 21(1,-3.4) 22(1.4,-3.4) 36(1.8,3.4) 37(1.4,3.4) 38(1,3.4) 39(0.6,3.4) 40(0.2,3.4) 41(-0.2,3.4) 42(-0.6,3.4) 43(-1,3.4) 44(-1.4,3.4) 45(-1.8,3.4)
  rrect5% 3.7x2.1 smd paste-2: 46(0,1.4)
  rrect5% 2.9x2.15 smd paste-2: 47(0,-1.375)
  body extent -2.55,-3.55 2.55,3.55, height 1.01
SM_RADIAL_F [mm] "8 x 10.2mm:  Panasonic F"
  rect 4x2 smd: 1(-3.55,0) 2(3.55,0)
  silkscreen extent -4.25,-4.25 4.25,4.25, body extent -4.25,-4.25 4.25,4.25, height 10.5
SM_RADIAL_G [mm] "10 x 10.2mm:  Panasonic G"
  rect 4.1x2 smd: 1(-4.35,0) 2(4.35,0)
  silkscreen extent -5.35,-5.35 5.35,5.35, body extent -5.25,-5.25 5.25,5.25, height 10.5
SMA [mm] "Molded Diode, 2-Leads, Body 4.3x2.6mm, IPC Medium Density, based on OnSemi component dimensions and land pattern"
  rect 2x2 smd: 1(-2,0) 2(2,0)
  silkscreen extent -3.66,-1.57 2.79,1.57, body extent -2.6,-1.3 2.6,1.3, height 2.42
SMB [mil] "Molded Diode, 2-Leads, Body 5.4x3.6mm, IPC Medium Density, based on OnSemi component dimensions"
  rect 85x107.99 smd: 1(-87.01,0) 2(87.01,0)
  silkscreen extent -155,-82 125,82, body extent -106,-71 106,71, height 91
SOD-123 [mm] "On Semi recommended land pattern"
  rect 0.915x1.22 smd: 1(-1.637,0) 2(1.637,0)
  silkscreen extent -2.74,-1.17 2.03,1.17, body extent -1.93,-0.9 1.93,0.9, height 1.35
SOD-323 [mm] "NXP recommended land pattern"
  rect 0.6x0.6 smd paste-0.05: 1(-1.1,0) 2(1.1,0)
  silkscreen extent -2.06,-0.86 1.53,0.86, body extent -1.3,-0.67 1.3,0.68, height 1.1
SOT-23L [mm] "SOT23, 3-Leads, Body 2.9x1.3mm, Pitch 0.95mm, Lead Span 2.5mm, IPC High Density"
  rrect50% 0.8x0.6 smd: 1(-1.1,0.95) 2(-1.1,-0.95) 3(1.1,0)
  silkscreen extent -1.5,-1.5 0.7,1.5, body extent -1.16,-1.45 1.21,1.45, height 1
SOT-363 [mm]
  rect 0.6x0.42 smd mask+0.051: 1(-0.95,0.65) 2(-0.95,0) 3(-0.95,-0.65) 4(0.95,-0.65) 5(0.95,0) 6(0.95,0.65)
  silkscreen extent -0.38,-1.02 0.38,1.02, body extent -1.1,-1.1 1.1,1.1, height 1.12
TEC_1-406541-1 [mm] "TE Connectivity"
  round 1.4 hole 0.89: 1(3.56,-0.18) 2(2.54,1.6) 3(1.52,-0.18) 4(0.5,1.6) 5(-0.52,-0.18) 6(-1.54,1.6) 7(-2.56,-0.18) 8(-3.58,1.6)
  round 2.1 hole 1.57: 9(8.12,0.71) 10(-8.14,0.71)
  round 3.759 hole 3.251: 11(6.34,-2.72) 12(-6.36,-2.72)
  silkscreen extent -9.69,-8 9.69,8.06, body extent -9.33,-8 9.31,7.75, height 14.8
TERM_BLK_ED555-2DS [mil]
  rrect4% 100x100 hole 50: 1(0,0)
  round 100 hole 50: 2(138,0)
  silkscreen extent -93,-161 215,113, body extent -69,-150 207,106, height 323
TO-277A [mm] "Vishay"
  rect 1.4x1.27 smd: 1(-1.04,1.83) 2(1.04,1.83)
  rect 4.72x4.8 smd: 3(0,-1.883)
  silkscreen extent -2.7,1.45 -2.4,1.75, body extent -2.35,-4.2 2.4,2.45, height 1.2
TRANS_Fairchild_PQFN08A [mm] "Fairchild PQFN08A recommended land pattern"
  rect 1.27x0.61 smd: 1(-2.67,1.905) 2(-2.67,0.635) 3(-2.67,-0.635) 4(-2.67,-1.905) 5(2.67,-1.905) 6(2.67,-0.635) 7(2.67,0.635) 8(2.67,1.905)
  Top Layer region: -1.215,-2.55 2.535,-2.55 2.535,2.55 -1.215,2.55
  silkscreen extent -3.2,-2.7 3.2,2.7, body extent -3.05,-2.55 3.05,2.55, height 1.11
TSW-102-07-G-S [mm] "Samtec 100mil, 1x2, 230 mil above insulator"
  rrect50% 1.65x1.65 hole 1.016: 1(-1.27,0)
  round 1.65 hole 1.016: 2(1.27,0)
  silkscreen extent -3.17,-1.27 2.54,1.27, body extent -2.54,-1.27 2.54,1.27, height 8.38
WE-SL5 [mm] "SMD, 4-Leads, Body 8.7x10mm"
  rect 2.7x2.7 smd: 1(-3.11,3.81) 2(-3.11,-3.81) 3(3.11,-3.81) 4(3.11,3.81)
  silkscreen extent -4.35,-5 4.35,5.4, body extent -4.35,-5 4.35,5, height 6
WE-SL5_HC [mm] "SMD, 4-Leads, Body 9.5x8.3mm"
  rect 2.7x2.7 smd: 1(-3.8,3.1) 2(-3.8,-3.1) 3(3.8,-3.1) 4(3.8,3.1)
  silkscreen extent -5.2,-4.15 4.75,4.15, body extent -4.75,-4.15 4.75,4.15, height 5.31
WEEE_Minimum [mil] "WEEElie bin"
  silkscreen extent -95,-172 99,104
XFMR_749022016 [mil] "XFMR_SOIC-24_WIDE, 0.050mil pitch"
  oval 103x24 smd: 1(-286,275) 2(-286,225) 3(-286,175) 4(-286,125) 5(-286,75) 6(-286,25) 7(-286,-25) 8(-286,-75) 9(-286,-125) 10(-286,-175) 11(-286,-225) 12(-286,-275) 13(286,-275) 14(286,-225) 15(286,-175) 16(286,-125) 17(286,-75) 18(286,-25) 19(286,25) 20(286,75) 21(286,125) 22(286,175) 23(286,225) 24(286,275)
  silkscreen extent -205,-365 204,365, body extent -259,-363 258,362, height 401

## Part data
C1 C6: library part CMP-0009438-2, "CAP, CERM, 1000 pF, 2000 V, +/- 10%, X7R, 1812", Cap_Case=1812, Manufacturer=MuRata, TempCo=X7R, Tolerance_%=10%, Value1=Unknown, Value2=2000V, ValueDisplayed=1000pF
C2 C3 C4 C5: library part CMP-0007468-5, "CAP, CERM, 0.01 uF, 100 V, +/- 10%, X7R, 0603", Cap_Case=0603, Manufacturer=MuRata, PartNumber=GRM188R72A103KA01D, Supplier Part Number 1=GRM188R72A103KA01D-ND, TempCo=X7R, Tolerance_%=10%, Value1=Unknown, Value2=100V, ValueDisplayed=0.01uF
C7 C8: library part CMP-0007053-4, "CAP, CERM, 1000 pF, 100 V, +/- 10%, X7R, 0603", Cap_Case=0603, Manufacturer=TDK, Supplier Part Number 1=445-1298-1-ND, TempCo=X7R, Tolerance_%=10%, Value1=Unknown, Value2=100V, ValueDisplayed=1000pF
C9 C10 C11 C18 C50: library part CMP-0064933-4, "CAP, CERM, 1000 pF, 50 V,+/- 10%, X7R, 0603", Cap_Case=0603, Manufacturer="Wurth Elektronik", Supplier Part Number 1=732-8001-1-ND, TempCo=X7R, Tolerance_%=10%, Value1=Unknown, Value2=50V, ValueDisplayed=1000pF
C12 C38: library part CMP-0007397-4, "CAP, CERM, 0.047 uF, 16 V, +/- 10%, X7R, 0603", Cap_Case=0603, Manufacturer=MuRata, Supplier Part Number 1=490-1529-1-ND, TempCo=X7R, Tolerance_%=10%, Value1=Unknown, Value2=16V, ValueDisplayed=0.047uF
C13: library part CMP-0007221-4, "CAP, CERM, 470 pF, 50 V, +/- 5%, C0G/NP0, 0603", Cap_Case=0603, Manufacturer=MuRata, Supplier Part Number 1=490-1443-1-ND, TempCo=C0G/NP0, Tolerance_%=5%, Value1=Unknown, Value2=50V, ValueDisplayed=470pF
C14 C16: library part CMP-0007433-4, "CAP, CERM, 0.01 uF, 50 V, +/- 10%, X7R, 0603", Cap_Case=0603, Manufacturer=MuRata, Supplier Part Number 1=490-1512-1-ND, TempCo=X7R, Tolerance_%=10%, Value1=Unknown, Value2=50V, ValueDisplayed=0.01uF
C15 C36 C40 C44: library part CMP-0079720-1, "CAP, CERM, 1 µF, 25 V,+/- 10%, X7R, 0603", Cap_Case=0603, Manufacturer=MuRata, Supplier Part Number 1=490-10888-1-ND, TempCo=X7R, Tolerance_%=10%, Value2=25V, ValueDisplayed=1µF
C17: library part CMP-0007203-4, "CAP, CERM, 270 pF, 50 V, +/- 5%, C0G/NP0, 0603", Cap_Case=0603, Manufacturer=MuRata, Supplier Part Number 1=490-1437-1-ND, TempCo=C0G/NP0, Tolerance_%=5%, Value1=Unknown, Value2=50V, ValueDisplayed=270pF
C19 C20 C45 C47: library part CMP-0006856-6, "CAP, CERM, 0.1 uF, 25 V, +/- 5%, X7R, 0603", Cap_Case=0603, Manufacturer=Kemet, Supplier Part Number 1=399-1282-1-ND, TempCo=X7R, Tolerance_%=5%, Value1=Unknown, Value2=25V, ValueDisplayed=0.1uF
C21 C22: library part CMP-0009358-2, "CAP, CERM, 2200 pF, 2000 V, +/- 10%, X7R, 1812", Cap_Case=1812, Manufacturer=TDK, PartNumber=C4532X7R3D222K130KA, Supplier Part Number 1=445-2389-1-ND, TempCo=X7R, Tolerance_%=10%, Value1=Unknown, Value2=2000V, ValueDisplayed=2200pF
C23: library part CMP-0011200-2, "CAP, AL, 47 uF, 80 V, +/- 20%, 0.7 ohm, AEC-Q200 Grade 2, SMD", Cap_Case=G, Manufacturer=Panasonic, Supplier Part Number 1=PCE3831CT-ND, Tolerance_%=20%, Value1="0.7 ohm", Value2=80V, ValueDisplayed=47uF
C24 C28 C39: library part CMP-0007886-2, "CAP, CERM, 0.1 uF, 100 V, +/- 10%, X7R, 0805", Cap_Case=0805, Manufacturer=TDK, PartNumber=C2012X7R2A104K125AA, Supplier Part Number 1=445-1418-1-ND, TempCo=X7R, Tolerance_%=10%, Value1="0.020726 ohm", Value2=100V, ValueDisplayed=0.1uF
C25 C26 C27: library part CMP-0009232-2, "CAP, CERM, 2.2 uF, 100 V, +/- 10%, X7R, 1210", Cap_Case=1210, Manufacturer=MuRata, PartNumber=GRM32ER72A225KA35L, Supplier Part Number 1=490-3385-1-ND, TempCo=X7R, Tolerance_%=10%, Value1="0.007 ohm", Value2=100V, ValueDisplayed=2.2uF
C29: library part CMP-0010714-1, "CAP, AL, 220 uF, 25 V, +/- 20%, 0.16 ohm, AEC-Q200 Grade 2, SMD", Cap_Case=F, Manufacturer=Panasonic, Supplier Part Number 1=PCE3800CT-ND, Tolerance_%=20%, Value1="0.16 ohm", Value2=25V, ValueDisplayed=220uF
C30 C31 C32 C33 C34 C35 C52 C53: library part CMP-0009224-2, "CAP, CERM, 22 uF, 25 V, +/- 10%, X7R, 1210", Cap_Case=1210, Manufacturer=MuRata, Supplier Part Number 1=490-5313-1-ND, TempCo=X7R, Tolerance_%=10%, Value1=Unknown, Value2=25V, ValueDisplayed=22uF
C37: library part CMP-0006737-4, "CAP, CERM, 2200 pF, 100 V, +/- 10%, X7R, 0603", Cap_Case=0603, Manufacturer=AVX, Supplier Part Number 1=478-1201-1-ND, TempCo=X7R, Tolerance_%=10%, Value1="0.192 ohm", Value2=100V, ValueDisplayed=2200pF
C41: library part CMP-0007045-5, "CAP, CERM, 0.015 uF, 50 V, +/- 10%, X7R, AEC-Q200 Grade 1, 0603", Cap_Case=0603, Manufacturer=TDK, Supplier Part Number 1=445-5189-1-ND, TempCo=X7R, Tolerance_%=10%, Value1=Unknown, Value2=50V, ValueDisplayed=0.015uF
C43: library part CMP-0007442-5, "CAP, CERM, 220 pF, 50 V, +/- 10%, X7R, 0603", Cap_Case=0603, Manufacturer=MuRata, Supplier Part Number 1=490-1483-1-ND, TempCo=X7R, Tolerance_%=10%, Value1=Unknown, Value2=50V, ValueDisplayed=220pF
C46: library part CMP-0006897-4, "CAP, CERM, 2200 pF, 50 V, +/- 10%, X7R, 0603", Cap_Case=0603, Manufacturer=Kemet, Supplier Part Number 1=1362428, TempCo=X7R, Tolerance_%=10%, Value1=Unknown, Value2=50V, ValueDisplayed=2200pF
C49: library part CMP-0008236-2, "CAP, CERM, 100 pF, 250 V, +/- 5%, C0G/NP0, 0805", Cap_Case=0805, Manufacturer=MuRata, Supplier Part Number 1=490-5542-1-ND, TempCo=C0G/NP0, Tolerance_%=5%, Value1=Unknown, Value2=250V, ValueDisplayed=100pF
C51: library part CMP-0006822-4, "CAP, CERM, 100 pF, 50 V, +/- 5%, C0G/NP0, 0603", Cap_Case=0603, Manufacturer="Wurth Elektronik", TempCo=C0G/NP0, Tolerance_%=5%, Value1=Unknown, Value2=50V, ValueDisplayed=100pF
D1 D2 D3 D4 D5 D6 D7 D8: "Diode, Schottky, 100 V, 2 A, SMB", Manufacturer="Diodes Inc.", PartNumber=B2100-13-F, Value1=2A, Value2=0.79V
D9: library part CMP-0029006-2, "Diode, Ultrafast, 100 V, 0.25 A, SOD-323", Manufacturer=Nexperia, Value1=0.25A, Value2=1.4V
D10: library part CMP-0028634-2, "Diode, Schottky, 40 V, 10 A, PowerDI5", Manufacturer="Diodes Inc.", Value1=10A, Value2=0.49V
D11: library part CMP-0028980-2, "Diode, Schottky, 60 V, 10 A, TO-277A", Manufacturer="Fairchild Semiconductor", Value1=10A, Value2=0.52V
D12: library part CMP-0029024-2, "Diode, Ultrafast, 200 V, 1 A, SMA", Manufacturer="Diodes Inc.", Value1=1A, Value2=0.92V
D13: library part CMP-0005583-3, "Diode, TVS, Uni, 58 V, 93.6 Vc, SMB", Manufacturer="Diodes Inc.", Value1=600W
D14 D15: library part CMP-0029032-2, "Diode, Switching, 100 V, 0.2 A, SOD-123", Manufacturer="ON Semiconductor", Value1=0.2A, Value2=1V
D17 D18: library part CMP-0005922-4, "Diode, TVS, Uni, 27 V, SOT-23", Manufacturer="ON Semiconductor", Value1=40W
J1 J2: library part CMP-0054918-1, "RJ45, No LED, tab up, R/A, TH", Color=Black, Manufacturer="TE Connectivity", Supplier Part Number 1=A97716-ND
J3 J4 J10 J12: library part CMP-0055047-1, "Shorting Jumper, 2.54mm, 2 Position, Gold, TH", Manufacturer=Mill-Max, Supplier Part Number 1=ED1332-ND
J5 J6 J7 J8 J9 J14: library part CMP-0075405-3, "Header, 100mil, 2x1, Gold, TH", Color=Black, Current_A=6.3A, Manufacturer=Samtec, Supplier Part Number 1=SAM1029-02-ND, Voltage_V=550V
J11: "Terminal Block, 3.5mm Pitch, 2x1, TH", Color=Grey, Current_A=6A, Manufacturer="On-Shore Technology", PartNumber=ED555/2DS, Supplier Part Number 1=ED1514-ND, Voltage_V=150V
J13: library part CMP-0074913-1, "Terminal Block, 3.5mm Pitch, 2x1, TH", Color=Grey, Current_A=6A, Manufacturer="On-Shore Technology", PartNumber=ED555/2DS, Supplier Part Number 1=ED1514-ND, Voltage_V=150V
L1 L3: "Ferrite Bead, 300 ohm @ 100 MHz, 2 A, 0603", Manufacturer="Wurth Elektronik", PartNumber=742792641, Supplier Part Number 1=732-1592-1-ND, Value1="0.15 ohm", Value2=2A, ValueDisplayed="300 ohm"
L2: library part CMP-0013220-2, "Coupled inductor, 250 uH,  A, 0.035 ohm, SMD", Manufacturer="Wurth Elektronik", Supplier Part Number 1=732-1491-1-ND, ValueDisplayed=250uH
L4 L6: library part CMP-0003114-1, "Ferrite Bead, 80 ohm @ 100 MHz, 4 A, 1206", Manufacturer="Wurth Elektronik", Supplier Part Number 1=732-1630-1-ND, Value1="0.025 ohm", Value2=4A, ValueDisplayed="80 ohm"
L5: library part CMP-0013075-2, "Coupled inductor, 5 uH,  A, 0.0055 ohm, SMD", Manufacturer="Wurth Elektronik", Supplier Part Number 1=732-2214-1-ND, ValueDisplayed=5uH
L7: library part CMP-0060473-1, "Inductor, Shielded Drum Core, Ferrite, 3.3 uH, 1.9 A, 0.08 ohm, SMD", Manufacturer=Coilcraft, Value1="0.08 ohm", Value2=1.9A, ValueDisplayed=3.3uH
Logo1: library part CMP-0074769-1
Logo2: library part CMP-0074847-1, "FCC_disclaimer"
